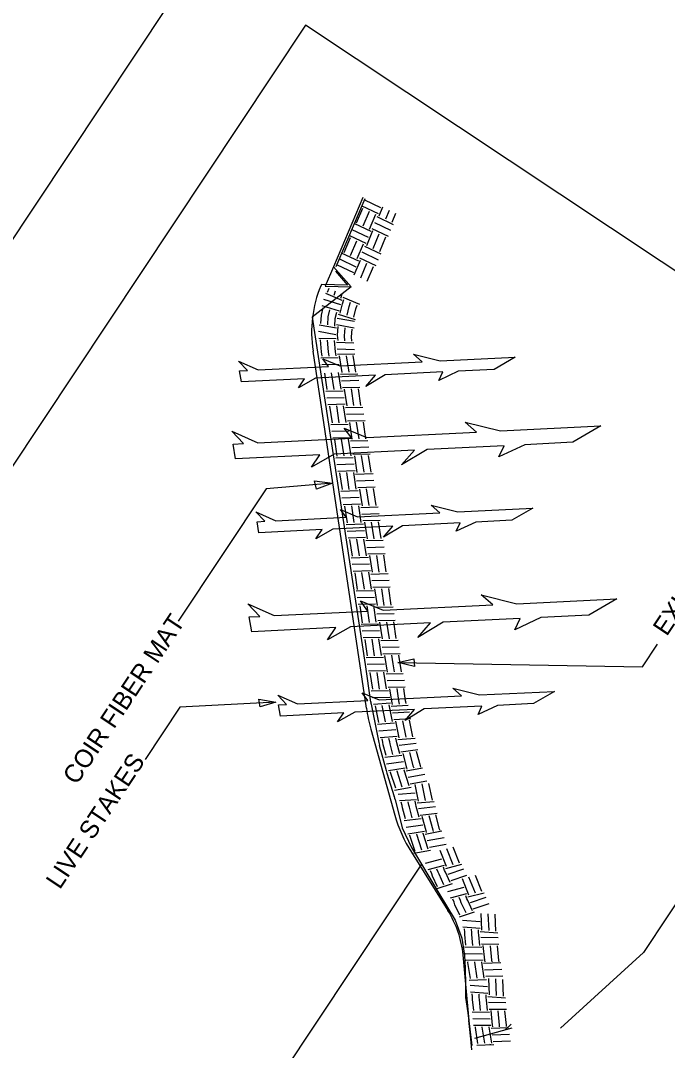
# Model space of a CAD drawing. Extents: x 561231 to 564935, y 589159 to 602519.
# Drawn here: x 564299.4 to 564400.8, y 589419.8 to 589581.1 of the extents above; entities that cross this region are included whole.
import ezdxf

# ---------------------------------------------------------------- set-up
doc = ezdxf.new("R2010")
doc.units = 0
doc.layers.add('Old_Level_1', color=7, linetype='Continuous')

msp = doc.modelspace()

# ---------------------------------------------------------------- linework, layer by layer
at = {"layer": 'Old_Level_1'}
for p, q in [((564352.9, 589552.13), (564355.46, 589550.93)), ((564353.31, 589553.06), (564355.84, 589551.85)), ((564355.25, 589550.45), (564357.81, 589549.23)), ((564351.73, 589549.35), (564354.29, 589548.15)), ((564354.85, 589549.52), (564357.4, 589548.32)), ((564350.96, 589547.51), (564353.51, 589546.29)), ((564351.32, 589548.44), (564353.9, 589547.21)), ((564354.46, 589548.59), (564357.01, 589547.4)), ((564353.3, 589545.83), (564355.86, 589544.62)), ((564349.77, 589544.74), (564352.35, 589543.53)), ((564352.51, 589543.97), (564355.07, 589542.77)), ((564352.88, 589544.92), (564355.47, 589543.7)), ((564349.01, 589542.88), (564351.56, 589541.67)), ((564349.39, 589543.81), (564351.95, 589542.59)), ((564346.86, 589537.51), (564349.56, 589536.68)), ((564347.19, 589538.47), (564349.78, 589537.37)), ((564349.93, 589537.81), (564352.53, 589536.71)), ((564346.65, 589536.53), (564349.32, 589535.69)), ((564349.01, 589534.55), (564351.75, 589534.07)), ((564349.18, 589535.18), (564351.86, 589534.34)), ((564346.19, 589533.51), (564348.92, 589533.02)), ((564348.93, 589533.52), (564351.67, 589533.04)), ((564346.11, 589532.48), (564348.83, 589532)), ((564346.15, 589531.43), (564348.88, 589531.34)), ((564348.92, 589530.79), (564351.63, 589530.68)), ((564349, 589529.74), (564351.72, 589529.63)), ((564345.24, 589529.38), (564353.58, 589473.47)), ((564346.46, 589528.32), (564349.17, 589528.39)), ((564349.06, 589528.88), (564351.79, 589528.95)), ((564346.62, 589527.27), (564349.34, 589527.35)), ((564349.56, 589525.75), (564352.27, 589525.84)), ((564349.71, 589524.72), (564352.43, 589524.81)), ((564347.26, 589523.1), (564349.98, 589523.16)), ((564349.88, 589523.67), (564352.58, 589523.74)), ((564347.41, 589522.05), (564350.12, 589522.13)), ((564347.56, 589521.03), (564350.29, 589521.1)), ((564350.33, 589520.54), (564353.06, 589520.62)), ((564350.5, 589519.49), (564353.22, 589519.57)), ((564350.67, 589518.45), (564353.39, 589518.53)), ((564348.06, 589517.88), (564350.76, 589517.95)), ((564348.21, 589516.84), (564350.92, 589516.91)), ((564348.36, 589515.8), (564351.07, 589515.87)), ((564351.14, 589515.34), (564353.85, 589515.4)), ((564351.3, 589514.29), (564354, 589514.36)), ((564351.46, 589513.25), (564354.17, 589513.31)), ((564348.83, 589512.67), (564351.54, 589512.73)), ((564348.99, 589511.63), (564351.71, 589511.7)), ((564349.15, 589510.59), (564351.87, 589510.66)), ((564351.92, 589510.11), (564354.64, 589510.2)), ((564352.07, 589509.08), (564354.79, 589509.16)), ((564349.62, 589507.46), (564352.34, 589507.53)), ((564352.25, 589508.03), (564354.96, 589508.1)), ((564349.78, 589506.41), (564352.49, 589506.48)), ((564349.95, 589505.37), (564352.66, 589505.43)), ((564352.74, 589504.9), (564355.44, 589504.97)), ((564352.88, 589503.85), (564355.59, 589503.93)), ((564350.43, 589502.24), (564353.13, 589502.31)), ((564353.04, 589502.82), (564355.75, 589502.89)), ((564350.58, 589501.19), (564353.29, 589501.28)), ((564350.74, 589500.14), (564353.44, 589500.22)), ((564353.51, 589499.69), (564356.22, 589499.77)), ((564353.67, 589498.64), (564356.39, 589498.71)), ((564353.83, 589497.6), (564356.54, 589497.68)), ((564351.21, 589497.02), (564353.92, 589497.08)), ((564351.37, 589495.98), (564354.08, 589496.04)), ((564351.53, 589494.93), (564354.23, 589495.02)), ((564354.29, 589494.46), (564357, 589494.53)), ((564354.46, 589493.43), (564357.18, 589493.5)), ((564354.63, 589492.38), (564357.33, 589492.45)), ((564352, 589491.81), (564354.71, 589491.89)), ((564352.15, 589490.77), (564354.87, 589490.84)), ((564352.33, 589489.73), (564355.03, 589489.78)), ((564355.1, 589489.25), (564357.8, 589489.33)), ((564355.25, 589488.2), (564357.96, 589488.28)), ((564352.79, 589486.6), (564355.5, 589486.67)), ((564355.41, 589487.17), (564358.11, 589487.24)), ((564352.93, 589485.55), (564355.66, 589485.62)), ((564353.11, 589484.5), (564355.83, 589484.58)), ((564355.89, 589484.04), (564358.59, 589484.12)), ((564356.06, 589482.98), (564358.75, 589483.07)), ((564353.58, 589481.37), (564356.29, 589481.44)), ((564356.19, 589481.95), (564358.91, 589482.03)), ((564353.75, 589480.34), (564356.46, 589480.4)), ((564353.91, 589479.29), (564356.61, 589479.36)), ((564356.68, 589478.82), (564359.37, 589478.89)), ((564356.84, 589477.78), (564359.55, 589477.85)), ((564354.37, 589476.16), (564357.08, 589476.24)), ((564357, 589476.74), (564359.7, 589476.81)), ((564354.53, 589475.11), (564357.26, 589475.18)), ((564354.34, 589474.08), (564355.56, 589468.05)), ((564354.7, 589474.07), (564357.4, 589474.28)), ((564357.48, 589473.74), (564360.16, 589473.94)), ((564357.7, 589472.7), (564360.38, 589472.89)), ((564357.9, 589471.67), (564360.59, 589471.85)), ((564354.32, 589470.15), (564358.07, 589456.7)), ((564355.33, 589470.96), (564358.01, 589471.16)), ((564355.53, 589469.91), (564358.24, 589470.12)), ((564355.75, 589468.87), (564358.44, 589469.07)), ((564358.54, 589468.55), (564361.22, 589468.74)), ((564355.63, 589467.67), (564356.69, 589463.66)), ((564358.75, 589467.64), (564361.41, 589467.99)), ((564359.01, 589466.61), (564361.67, 589466.95)), ((564356.51, 589465.77), (564359.17, 589466.11)), ((564356.77, 589464.75), (564359.43, 589465.09)), ((564357.06, 589463.69), (564359.68, 589464.11)), ((564359.81, 589463.64), (564362.41, 589464.12)), ((564356.79, 589463.28), (564357.97, 589459.62)), ((564360.13, 589462.62), (564362.75, 589463.1)), ((564360.46, 589461.59), (564363.08, 589462.08)), ((564358.03, 589460.62), (564360.62, 589461.1)), ((564358.57, 589460), (564361.25, 589460.2)), ((564358.1, 589459.15), (564359.2, 589454.69)), ((564358.78, 589458.96), (564361.47, 589459.15)), ((564361.56, 589458.61), (564364.24, 589458.82)), ((564361.77, 589457.74), (564364.42, 589458.07)), ((564362.05, 589456.69), (564364.7, 589457.02)), ((564359.52, 589455.86), (564362.19, 589456.19)), ((564359.2, 589454.69), (564360.68, 589451.64)), ((564359.82, 589454.82), (564362.47, 589455.16)), ((564360.07, 589453.78), (564362.71, 589454.2)), ((564362.83, 589453.72), (564365.44, 589454.21)), ((564363.15, 589452.71), (564365.78, 589453.19)), ((564363.5, 589451.68), (564366.11, 589452.16)), ((564360.66, 589450.88), (564366.36, 589441.78)), ((564360.68, 589451.64), (564364.97, 589444.46)), ((564361.06, 589450.71), (564363.66, 589451.19)), ((564362.22, 589449.01), (564323.73, 589391.1)), ((564362.88, 589449.17), (564365.41, 589449.86)), ((564363.28, 589448.17), (564365.84, 589448.85)), ((564366.03, 589448.33), (564368.57, 589449)), ((564366.41, 589447.47), (564368.89, 589448.27)), ((564366.86, 589446.48), (564369.34, 589447.29)), ((564364.4, 589445.65), (564364.4, 589445.65)), ((564364.68, 589445.21), (564367.07, 589446)), ((564364.97, 589444.46), (564367.49, 589440.26)), ((564366.37, 589444.73), (564368.92, 589445.42)), ((564366.78, 589443.73), (564369.33, 589444.4)), ((564369.51, 589443.88), (564372.06, 589444.54)), ((564369.9, 589443.02), (564372.37, 589443.83)), ((564370.35, 589442.03), (564372.85, 589442.85)), ((564367.88, 589441.19), (564367.88, 589441.19)), ((564368.17, 589440.77), (564370.56, 589441.54)), ((564367.49, 589440.26), (564368.57, 589437.4)), ((564368.67, 589440.24), (564371.4, 589440.03)), ((564368.7, 589439.18), (564371.45, 589438.99)), ((564371.45, 589438.44), (564374.18, 589438.25)), ((564371.52, 589437.56), (564374.25, 589437.51)), ((564368.57, 589437.4), (564368.99, 589434.73)), ((564368.96, 589436.05), (564371.7, 589436.01)), ((564371.62, 589436.51), (564374.35, 589436.46)), ((564368.73, 589434.82), (564370.07, 589419.93)), ((564368.99, 589434.73), (564369.09, 589432.71)), ((564369.08, 589435.01), (564371.8, 589434.96)), ((564369.09, 589432.71), (564369.14, 589430.06)), ((564369.2, 589433.98), (564371.91, 589434.01)), ((564369.61, 589433.75), (564369.61, 589433.75)), ((564371.96, 589433.52), (564374.67, 589433.61)), ((564372.12, 589432.47), (564374.81, 589432.58)), ((564372.3, 589431.45), (564374.99, 589431.54)), ((564369.14, 589430.06), (564369.15, 589428.11)), ((564369.68, 589430.84), (564372.4, 589430.93)), ((564369.86, 589430.04), (564372.57, 589429.86)), ((564369.15, 589428.11), (564369.5, 589425.72)), ((564369.9, 589429), (564372.63, 589428.82)), ((564372.65, 589428.28), (564375.39, 589428.09)), ((564370.39, 589426.45), (564370.39, 589426.45)), ((564372.72, 589427.38), (564375.45, 589427.34)), ((564372.82, 589426.32), (564375.56, 589426.29)), ((564369.5, 589425.72), (564370.13, 589420.63)), ((564370.17, 589425.88), (564372.9, 589425.82)), ((564370.27, 589424.83), (564373.01, 589424.8)), ((564369.59, 589424.51), (564369.98, 589421.18)), ((564370.37, 589423.8), (564373.11, 589423.82)), ((564373.16, 589423.35), (564375.87, 589423.44)), ((564373.32, 589422.3), (564376.03, 589422.4)), ((564370.89, 589420.66), (564373.59, 589420.76)), ((564373.48, 589421.26), (564376.2, 589421.35))]:
    msp.add_line(p, q, dxfattribs=at)
for points in [[(564040.89, 589558.02), (564144.12, 589713.34), (564327.69, 589591.34), (564224.45, 589436.03)], [(564424.04, 589303.41), (564527.25, 589458.73), (564344.07, 589580.44), (564240.86, 589425.13)], [(564347.17, 589539.54), (564351.22, 589539.46), (564348.46, 589542.6)], [(564334.02, 589524.57), (564333.71, 589526.28), (564334.96, 589526.35), (564333.57, 589527.81), (564336.65, 589526.43), (564347.67, 589526.97), (564346.8, 589528.19), (564349.46, 589527.06), (564362.35, 589527.71), (564360.99, 589528.89), (564365.15, 589527.84), (564376.93, 589528.42), (564373.64, 589526.51), (564368, 589526.23), (564364.93, 589524.79), (564365.56, 589526.11), (564356.53, 589525.67), (564353.52, 589523.86), (564355.02, 589525.6), (564345.62, 589525.12), (564342.95, 589523.6), (564343.93, 589525.02)], [(564333.12, 589512.48), (564332.71, 589514.81), (564334.37, 589514.88), (564332.51, 589516.83), (564336.62, 589515), (564351.3, 589515.72), (564350.14, 589517.33), (564353.69, 589515.82), (564370.87, 589516.68), (564369.07, 589518.27), (564374.63, 589516.88), (564390.34, 589517.65), (564385.94, 589515.09), (564378.41, 589514.72), (564374.34, 589512.8), (564375.17, 589514.56), (564363.12, 589513.97), (564359.12, 589511.57), (564361.13, 589513.87), (564348.58, 589513.26), (564345.01, 589511.22), (564346.32, 589513.12)], [(564345.48, 589509.08), (564348.32, 589508.7), (564345.79, 589507.76)], [(564336.77, 589500.92), (564336.47, 589502.65), (564337.71, 589502.74), (564336.31, 589504.18), (564339.41, 589502.81), (564350.42, 589503.35), (564349.53, 589504.55), (564352.2, 589503.43), (564365.09, 589504.07), (564363.74, 589505.25), (564367.91, 589504.21), (564379.7, 589504.78), (564376.4, 589502.88), (564370.75, 589502.6), (564367.69, 589501.18), (564368.3, 589502.49), (564359.27, 589502.03), (564356.28, 589500.23), (564357.77, 589501.96), (564348.36, 589501.49), (564345.69, 589499.99), (564346.67, 589501.41)], [(564335.64, 589485.42), (564335.23, 589487.76), (564336.89, 589487.81), (564335.03, 589489.77), (564339.16, 589487.94), (564353.84, 589488.66), (564352.66, 589490.27), (564356.21, 589488.79), (564373.39, 589489.63), (564371.58, 589491.22), (564377.15, 589489.81), (564392.85, 589490.6), (564388.46, 589488.04), (564380.95, 589487.66), (564376.86, 589485.74), (564377.68, 589487.51), (564365.65, 589486.91), (564361.64, 589484.53), (564363.64, 589486.82), (564351.11, 589486.18), (564347.53, 589484.16), (564348.84, 589486.08)], [(564361.16, 589479.95), (564358.52, 589480.6), (564361.04, 589481.17)], [(564340.17, 589472.21), (564339.86, 589473.96), (564341.11, 589474), (564339.72, 589475.46), (564342.79, 589474.11), (564353.81, 589474.64), (564352.94, 589475.86), (564355.6, 589474.74), (564368.49, 589475.37), (564367.13, 589476.56), (564371.3, 589475.53), (564383.09, 589476.08), (564379.78, 589474.18), (564374.16, 589473.89), (564371.09, 589472.44), (564371.7, 589473.76), (564362.68, 589473.32), (564359.67, 589471.52), (564361.15, 589473.25), (564351.77, 589472.8), (564349.08, 589471.29), (564350.07, 589472.71)], [(564336.77, 589474.87), (564339.43, 589474.4), (564336.98, 589473.66)]]:
    msp.add_lwpolyline(points, close=True, dxfattribs=at)
for points in [[(564353.05, 589553.45), (564348.46, 589542.6), (564351.22, 589539.46), (564345.13, 589534.71)], [(564348.89, 589542.62), (564353.41, 589553.29)], [(564352.06, 589549.46), (564353.04, 589551.77)], [(564353.1, 589548.98), (564354.07, 589551.28)], [(564354.1, 589548.49), (564355.08, 589550.81)], [(564355.6, 589550.56), (564356.2, 589551.97)], [(564356.63, 589550.08), (564357.21, 589551.48)], [(564357.65, 589549.58), (564358.24, 589551.01)], [(564353.65, 589545.94), (564354.61, 589548.25)], [(564354.68, 589545.44), (564355.63, 589547.76)], [(564355.69, 589544.97), (564356.66, 589547.29)], [(564350.1, 589544.84), (564351.09, 589547.15)], [(564351.12, 589544.36), (564352.11, 589546.65)], [(564352.17, 589543.87), (564353.14, 589546.18)], [(564351.68, 589541.31), (564352.68, 589543.63)], [(564352.72, 589540.84), (564353.69, 589543.13)], [(564353.74, 589540.34), (564354.71, 589542.65)], [(564348.77, 589541.88), (564350.64, 589539.73), (564346.55, 589539.8), (564346.55, 589539.8), (564346.46, 589539.57)], [(564347.5, 589538.59), (564347.76, 589539.26)], [(564348.54, 589538.14), (564348.78, 589538.81)], [(564349.58, 589537.68), (564349.83, 589538.37)], [(564346.45, 589533.71), (564346.56, 589535.01), (564346.82, 589536.17)], [(564349.51, 589535.34), (564349.85, 589536.76), (564350.09, 589537.48)], [(564350.59, 589535), (564350.91, 589536.38), (564351.14, 589537.03)], [(564351.64, 589534.68), (564351.94, 589535.99), (564352.18, 589536.58)], [(564345.13, 589534.71), (564353.41, 589480.28), (564354.27, 589474.41)], [(564347.55, 589533.5), (564347.64, 589534.75), (564347.9, 589535.84)], [(564348.65, 589533.3), (564348.72, 589534.5), (564348.97, 589535.5)], [(564349.16, 589531.05), (564349.09, 589531.88), (564349.19, 589533.22)], [(564350.25, 589530.99), (564350.18, 589531.76), (564350.28, 589533.03)], [(564351.34, 589530.96), (564351.29, 589531.63), (564351.38, 589532.84)], [(564346.67, 589528.56), (564346.57, 589529.28), (564346.42, 589531.15)], [(564347.76, 589528.6), (564347.65, 589529.28), (564347.52, 589531.1)], [(564348.85, 589528.62), (564348.75, 589529.26), (564348.61, 589531.06)], [(564349.8, 589526.02), (564349.39, 589528.64)], [(564350.88, 589526.06), (564350.47, 589528.66)], [(564351.97, 589526.1), (564351.55, 589528.69)], [(564347.45, 589523.34), (564347.08, 589525.94)], [(564348.55, 589523.36), (564348.16, 589525.98)], [(564349.65, 589523.4), (564349.25, 589526.01)], [(564350.58, 589520.81), (564350.18, 589523.42)], [(564351.66, 589520.84), (564351.27, 589523.45)], [(564352.75, 589520.88), (564352.35, 589523.49)], [(564348.27, 589518.14), (564347.86, 589520.76)], [(564349.36, 589518.16), (564348.95, 589520.78)], [(564350.43, 589518.19), (564350.03, 589520.8)], [(564351.38, 589515.6), (564350.99, 589518.19)], [(564352.45, 589515.62), (564352.06, 589518.23)], [(564353.52, 589515.65), (564353.15, 589518.27)], [(564349.04, 589512.91), (564348.65, 589515.53)], [(564350.13, 589512.96), (564349.73, 589515.57)], [(564351.23, 589512.97), (564350.82, 589515.59)], [(564352.16, 589510.38), (564351.77, 589512.99)], [(564353.25, 589510.42), (564352.85, 589513.03)], [(564354.34, 589510.43), (564353.92, 589513.04)], [(564349.85, 589507.71), (564349.45, 589510.29)], [(564350.91, 589507.72), (564350.54, 589510.34)], [(564352.01, 589507.77), (564351.62, 589510.37)], [(564348.32, 589508.7), (564337.9, 589507.81), (564324.12, 589487.1)], [(564352.97, 589505.16), (564352.56, 589507.77)], [(564354.03, 589505.19), (564353.64, 589507.8)], [(564355.13, 589505.22), (564354.72, 589507.84)], [(564350.64, 589502.49), (564350.25, 589505.1)], [(564351.71, 589502.52), (564351.33, 589505.13)], [(564352.81, 589502.55), (564352.41, 589505.16)], [(564353.76, 589499.96), (564353.35, 589502.56)], [(564354.82, 589499.98), (564354.42, 589502.59)], [(564355.9, 589500.01), (564355.51, 589502.63)], [(564351.43, 589497.25), (564351.03, 589499.88)], [(564352.51, 589497.3), (564352.1, 589499.92)], [(564353.6, 589497.33), (564353.2, 589499.94)], [(564354.54, 589494.73), (564354.13, 589497.35)], [(564355.62, 589494.76), (564355.23, 589497.36)], [(564356.7, 589494.79), (564356.31, 589497.39)], [(564352.22, 589492.06), (564351.82, 589494.67)], [(564353.3, 589492.09), (564352.89, 589494.71)], [(564354.39, 589492.11), (564353.98, 589494.73)], [(564355.33, 589489.52), (564354.94, 589492.13)], [(564356.4, 589489.55), (564356.01, 589492.15)], [(564357.5, 589489.57), (564357.1, 589492.18)], [(564353, 589486.84), (564352.61, 589489.46)], [(564354.09, 589486.88), (564353.7, 589489.48)], [(564355.16, 589486.9), (564354.78, 589489.51)], [(564356.12, 589484.3), (564355.72, 589486.92)], [(564357.22, 589484.32), (564356.81, 589486.94)], [(564358.29, 589484.36), (564357.89, 589486.99)], [(564355.97, 589481.68), (564355.57, 589484.29)], [(564353.79, 589481.63), (564353.41, 589484.22)], [(564354.89, 589481.66), (564354.49, 589484.27)], [(564358.52, 589480.6), (564396.87, 589479.94), (564399.22, 589483.48)], [(564356.91, 589479.1), (564356.72, 589480.37), (564356.51, 589481.7)], [(564357.99, 589479.12), (564357.8, 589480.39), (564357.59, 589481.73)], [(564359.08, 589479.14), (564358.89, 589480.42), (564358.67, 589481.76)], [(564354.6, 589476.4), (564354.19, 589479.02)], [(564355.68, 589476.43), (564355.29, 589479.05)], [(564356.76, 589476.47), (564356.36, 589479.08)], [(564357.7, 589474.02), (564357.65, 589474.29), (564357.6, 589474.54), (564357.3, 589476.49)], [(564358.78, 589474.09), (564358.72, 589474.35), (564358.67, 589474.59), (564358.4, 589476.51)], [(564359.85, 589474.17), (564359.8, 589474.43), (564359.75, 589474.62), (564359.47, 589476.54)], [(564339.43, 589474.4), (564324.4, 589473.61), (564318.95, 589465.43)], [(564355.54, 589471.21), (564355.01, 589473.81)], [(564356.62, 589471.3), (564356.1, 589473.89)], [(564357.69, 589471.37), (564357.16, 589473.97)], [(564358.75, 589468.81), (564358.22, 589471.41)], [(564359.84, 589468.89), (564359.29, 589471.49)], [(564360.9, 589468.98), (564360.38, 589471.57)], [(564356.71, 589466.05), (564356.24, 589467.73), (564356.17, 589468.1), (564356.06, 589468.62)], [(564357.76, 589466.17), (564357.31, 589467.86), (564357.25, 589468.19), (564357.14, 589468.68)], [(564358.82, 589466.32), (564358.38, 589468), (564358.31, 589468.3), (564358.2, 589468.77)], [(564419.89, 589469.64), (564396.99, 589435.2), (564383.99, 589423.32)], [(564362.12, 589464.2), (564362.07, 589464.41), (564361.47, 589466.66)], [(564360.01, 589463.87), (564359.95, 589464.11), (564359.35, 589466.37)], [(564361.07, 589464.04), (564360.99, 589464.28), (564360.42, 589466.52)], [(564358.19, 589460.91), (564357.4, 589463.39), (564357.38, 589463.45)], [(564359.23, 589461.1), (564358.45, 589463.58), (564358.42, 589463.63)], [(564360.29, 589461.27), (564359.5, 589463.74), (564359.48, 589463.78)], [(564361.76, 589458.9), (564361.26, 589461.49)], [(564362.86, 589458.98), (564362.34, 589461.58)], [(564363.94, 589459.04), (564363.4, 589461.64)], [(564359.71, 589456.13), (564359.28, 589457.83), (564359.21, 589458.19), (564359.07, 589458.71)], [(564360.78, 589456.27), (564360.34, 589457.94), (564360.25, 589458.27), (564360.16, 589458.78)], [(564361.86, 589456.39), (564361.41, 589458.07), (564361.33, 589458.37), (564361.23, 589458.86)], [(564363.04, 589453.96), (564362.97, 589454.21), (564362.36, 589456.48)], [(564364.09, 589454.11), (564364.04, 589454.35), (564363.44, 589456.6)], [(564365.15, 589454.29), (564365.07, 589454.51), (564364.5, 589456.76)], [(564362.27, 589451.19), (564361.48, 589453.66), (564361.45, 589453.71)], [(564363.3, 589451.37), (564362.52, 589453.84), (564362.51, 589453.87)], [(564361.23, 589450.98), (564360.42, 589453.48), (564360.39, 589453.53)], [(564366.17, 589448.65), (564365.16, 589451.16)], [(564367.19, 589448.92), (564366.18, 589451.43)], [(564368.2, 589449.19), (564367.19, 589451.7)], [(564364.75, 589445.48), (564363.97, 589447.13), (564363.83, 589447.48), (564363.63, 589447.97)], [(564365.73, 589445.8), (564364.99, 589447.44), (564364.84, 589447.75), (564364.64, 589448.24)], [(564366.74, 589446.15), (564365.98, 589447.75), (564365.86, 589448.04), (564365.68, 589448.52)], [(564371.7, 589444.73), (564370.69, 589447.26)], [(564369.67, 589444.18), (564368.66, 589446.71)], [(564370.68, 589444.47), (564369.67, 589447)], [(564370.23, 589441.7), (564369.48, 589443.3), (564369.36, 589443.59), (564369.17, 589444.05)], [(564368.22, 589441.05), (564367.48, 589442.66), (564367.33, 589443.04), (564367.13, 589443.52)], [(564369.24, 589441.37), (564368.47, 589442.98), (564368.34, 589443.3), (564368.15, 589443.79)], [(564371.71, 589438.69), (564371.6, 589441.3)], [(564372.81, 589438.62), (564372.69, 589441.21)], [(564373.9, 589438.54), (564373.79, 589441.16)], [(564369.2, 589436.3), (564369.04, 589438.02), (564369, 589438.38), (564368.97, 589438.89)], [(564370.3, 589436.27), (564370.12, 589437.98), (564370.1, 589438.3), (564370.08, 589438.81)], [(564371.39, 589436.27), (564371.22, 589437.94), (564371.18, 589438.24), (564371.16, 589438.72)], [(564372.2, 589433.73), (564372.17, 589433.97), (564371.92, 589436.25)], [(564373.28, 589433.73), (564373.25, 589433.95), (564373.02, 589436.23)], [(564374.38, 589433.73), (564374.35, 589433.94), (564374.12, 589436.21)], [(564369.89, 589431.1), (564369.48, 589433.63), (564369.47, 589433.7)], [(564370.98, 589431.14), (564370.57, 589433.66), (564370.57, 589433.7)], [(564372.07, 589431.18), (564371.67, 589433.66), (564371.66, 589433.71)], [(564372.91, 589428.53), (564372.79, 589431.12)], [(564374.01, 589428.45), (564373.88, 589431.04)], [(564375.08, 589428.35), (564374.99, 589430.97)], [(564370.41, 589426.11), (564370.22, 589427.83), (564370.2, 589428.21), (564370.16, 589428.71)], [(564371.49, 589426.1), (564371.3, 589427.8), (564371.28, 589428.14), (564371.27, 589428.64)], [(564372.59, 589426.08), (564372.4, 589427.78), (564372.37, 589428.06), (564372.37, 589428.56)], [(564373.4, 589423.52), (564373.37, 589423.79), (564373.14, 589426.07)], [(564374.48, 589423.54), (564374.45, 589423.78), (564374.22, 589426.05)], [(564375.57, 589423.56), (564375.53, 589423.78), (564375.3, 589426.04)], [(564376.38, 589423.33), (564370.56, 589421.73)], [(564371.08, 589420.92), (564370.69, 589423.45), (564370.67, 589423.51)], [(564372.18, 589420.95), (564371.76, 589423.46), (564371.76, 589423.52)], [(564373.27, 589420.99), (564372.86, 589423.49), (564372.86, 589423.53)], [(564376.29, 589423.93), (564375.38, 589423.12)], [(564372.99, 589420.77), (564373.06, 589420.85)]]:
    msp.add_lwpolyline(points, dxfattribs=at)
for centre, major_axis, start_param, end_param in [((564366.94, 589529.91), (-18.92, 12.57), 0.164799, 0.671881), ((564381.44, 589474.15), (-24.28, 16.13), 0.671881, 0.796341), ((564361.51, 589474.61), (-6.31, 4.19), 0.674198, 0.722692), ((564362.73, 589468.59), (-6.31, 4.19), 0.722692, 0.778668), ((564363.78, 589464.58), (-6.31, 4.19), 0.778668, 0.832789), ((564351, 589458.35), (6.31, -4.19), 0.762103, 0.832789), ((564378.86, 589459.77), (-18.61, 12.36), 0.796341, 1.09479), ((564353.09, 589435.29), (13.56, -9.01), 0.614806, 1.09479)]:
    msp.add_ellipse(centre, major_axis=major_axis, ratio=0.880425, start_param=start_param, end_param=end_param, dxfattribs=at)

# ---------------------------------------------------------------- texts
for s, p in [('EXISTING/PROPOSED', (564400.66, 589484.59)), ('COIR FIBER MAT', (564308.22, 589461.29)), ('LIVE STAKES', (564305.58, 589444.92))]:
    msp.add_text(s, height=2.8393, rotation=56.3664, dxfattribs=at).set_placement(p)

doc.saveas('drawing.dxf')
